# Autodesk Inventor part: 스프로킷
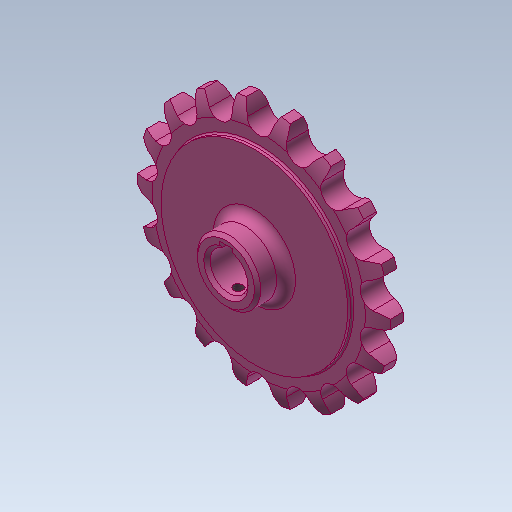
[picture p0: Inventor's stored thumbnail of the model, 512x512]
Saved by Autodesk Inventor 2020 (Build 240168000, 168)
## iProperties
Created: 2016-03
Part Number: 스프로킷
Material: 강철, 탄소
Document SubType Name: Modeling
Designer: mduedu
Density: 7.87 g/cm^3
Mass: 301.818 g
Surface Area: 124.882 cm^2
Volume: 38.3505 cm^3
Appearance: 분홍색
Author: mduedu
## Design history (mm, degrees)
sketch "스케치1"
  geometry: L1 (0, 5)-(29.5, 5); L2 (29.5, 5)-(29.5, 4.1); L3 (30, 3.6)-(33.625, 3.6); L4 (40, 2)-(40, 0); L5 (40, 0)-(0, 0); L6 (0, 0)-(0, 5); L7 (0, -5)-(29.5, -5); L8 (29.5, -5)-(29.5, -4.1); L9 (30, -3.6)-(33.625, -3.6); L10 (40, -2)-(40, 0); L11 (0, 0)-(0, -5); A1 r 13.5 centre (33.625, -9.9) between (40, 2) and (33.625, 3.6); A2 r 13.5 centre (33.625, 9.9) between (33.625, -3.6) and (40, -2); A3 r 0.5 centre (30, 4.1) between (29.5, 4.1) and (30, 3.6); A4 r 0.5 centre (30, -4.1) between (30, -3.6) and (29.5, -4.1); 2 further points
  constraints: 22 end point, 8 point on circle, 6 symmetric about line, 5 tangent, 4 centre point, 4 parallel, 4 point on line, 1 equal radius, 1 horizontal, 1 perpendicular, 1 other
  dimensions: "d0" = 80 diameter of L4 L6; "d2" = 59 diameter of L2 L6; "d3" = 1.6 vertical distance of L4.start L3.end; "d4" = 3.6 distance from line of L4.end L3; "d5" = 5 distance between parallel lines of L5 L1; "d6" = 13.5 radius of A1; "d15" = 0.5 radius of A3
revolve "회전1" sketch "스케치1" stored, may be unused: angle "d7" = 90 deg
sketch "스케치2" dims "d8" = 65.2, "d11" = 80
  geometry: L1 (0, 0)-(0, 32.6); A1 r 36.57 centre (0, 0) between (-16.231, 32.771) and (0, 36.57); A2 r 3.97 centre (0, 36.57) between (-3.866, 35.665) and (0, 32.6); A3 r 12.7 centre (-16.231, 32.771) between (-3.866, 35.665) and (-5.534, 39.615); A4 r 12.7 centre (16.231, 32.771) between (5.534, 39.615) and (3.866, 35.665); A5 r 3.97 centre (0, 36.57) between (0, 32.6) and (3.866, 35.665); A6 r 40 centre (0, 0) between (5.534, 39.615) and (-5.534, 39.615); 2 further points
  constraints: 12 point on circle, 6 centre point, 4 coincident, 3 symmetric about line, 2 end point, 1 point on line, 1 tangent, 1 vertical, 1 vertical alignment, 7 other
  dimensions: "d10" = 73.14 diameter of A1; "d12" = 12.7 radius of A3
extrude "돌출1" cut sketch "스케치2" extent not by distance; stored distance "d13" = 10; taper "d14" = 0 deg
sketch "스케치3"
  geometry: C1 r 10 at (0, 0); 1 further point
  constraints: 1 centre point, 1 coincident
  dimensions: "d19" = 20 diameter of C1
extrude "돌출2" join sketch "스케치3" distance "d20" = 9; taper "d21" = 0 deg
fillet "모깎기1" dims "d22" = 3
sketch "스케치4"
  geometry: L1 (-2, 0)-(2, 0); L2 (2, 0)-(2, 7.8); L3 (2, 7.8)-(-2, 7.8); L4 (-2, 7.8)-(-2, 0); C1 r 6 at (0, 0); 2 further points
  constraints: 8 end point, 2 coincident, 2 parallel, 1 centre point, 1 horizontal, 1 midpoint, 1 perpendicular
  dimensions: "d23" = 12 diameter of C1; "d25" = 4 distance of L2.end L3.end; "d26" = 7.8 distance of L1.end L2.end
extrude "돌출3" cut sketch "스케치4" extent not by distance; stored distance "d27" = 8; taper "d28" = 0 deg
chamfer "모따기2" distance "d42" = 1; stored, may be unused: second distance "d43" = 2, angle "d44" = 45 deg
node "작업 평면2"
sketch "스케치6"
  geometry: L1 (-9, 14)-(9, 14) reference; 3 further points
  constraints: 2 vertical alignment, 1 midpoint
  dimensions: "d59" = 4 distance from line of point (0, 10) L1
hole "구멍2" sketch "스케치6" at (0, 10) diameter "d48" = 3; stored, may be unused: countersink angle "d52" = 90 deg, drill point angle "d54" = 118 deg; dims "d49" = 6, "d50" = 4, "d51" = 2, "d53" = 8
thread "Thread1" dims "d56" = 10, "d57" = 0
node "솔리드1"
pattern_circular "원형 패턴1" dims angle "d17" = 360 deg
other parameters: "d55" = -13
